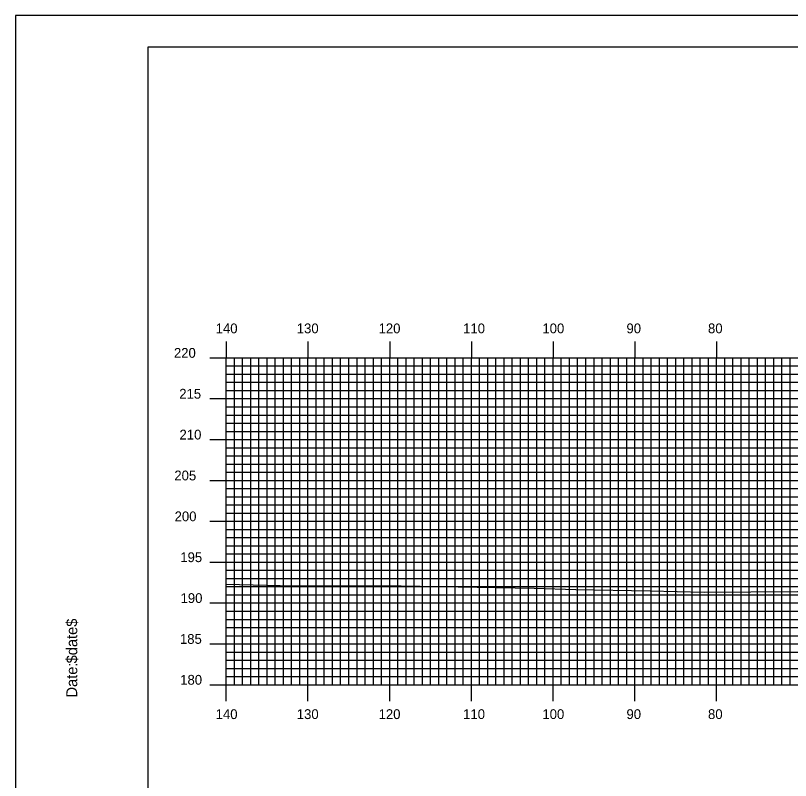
# Model space of a CAD drawing. Extents: x 1810980 to 1811323, y 442591 to 442811.
# Drawn here: x 1810980.1 to 1811074.9, y 442716.9 to 442810.5 of the extents above; entities that cross this region are included whole.
import ezdxf

# ---------------------------------------------------------------- set-up
doc = ezdxf.new("R2010")
doc.units = 0
for name, color, linetype in [('BORDER', 7, 'Continuous'), ('H_V ANNOTATION', 7, 'Continuous'), ('MAJOR', 7, 'Continuous'), ('MINOR', 7, 'Continuous'), ('PLOT BOUNDARY', 7, 'Continuous'), ('S_Roadway_Centerline', 7, 'Continuous')]:
    doc.layers.add(name, color=color, linetype=linetype)

msp = doc.modelspace()

# ---------------------------------------------------------------- linework, layer by layer
at = {"layer": 'BORDER'}
msp.add_lwpolyline([(1810996.29, 442596.665), (1811316.29, 442596.665), (1811316.29, 442806.665), (1810996.29, 442806.665)], close=True, dxfattribs=at)
at = {"layer": 'MAJOR'}
for p, q in [((1811005.89, 442770.669), (1811005.89, 442768.665)), ((1811015.89, 442770.669), (1811015.89, 442768.665)), ((1811025.89, 442770.669), (1811025.89, 442768.665)), ((1811035.89, 442770.669), (1811035.89, 442768.665)), ((1811045.89, 442770.669), (1811045.89, 442768.665)), ((1811055.89, 442770.669), (1811055.89, 442768.665)), ((1811065.89, 442770.669), (1811065.89, 442768.665)), ((1811003.886, 442768.665), (1811005.89, 442768.665)), ((1811005.89, 442768.665), (1811285.89, 442768.665)), ((1811005.89, 442728.665), (1811005.89, 442768.665)), ((1811005.89, 442728.665), (1811005.89, 442768.665)), ((1811005.89, 442768.665), (1811285.89, 442768.665)), ((1811015.89, 442728.665), (1811015.89, 442768.665)), ((1811025.89, 442728.665), (1811025.89, 442768.665)), ((1811035.89, 442728.665), (1811035.89, 442768.665)), ((1811045.89, 442728.665), (1811045.89, 442768.665)), ((1811055.89, 442728.665), (1811055.89, 442768.665)), ((1811065.89, 442728.665), (1811065.89, 442768.665)), ((1811003.886, 442763.665), (1811005.89, 442763.665)), ((1811005.89, 442763.665), (1811285.89, 442763.665)), ((1811003.886, 442758.665), (1811005.89, 442758.665)), ((1811005.89, 442758.665), (1811285.89, 442758.665)), ((1811003.886, 442753.665), (1811005.89, 442753.665)), ((1811005.89, 442753.665), (1811285.89, 442753.665)), ((1811003.886, 442748.665), (1811005.89, 442748.665)), ((1811005.89, 442748.665), (1811285.89, 442748.665)), ((1811003.886, 442743.665), (1811005.89, 442743.665)), ((1811005.89, 442743.665), (1811285.89, 442743.665)), ((1811003.886, 442738.665), (1811005.89, 442738.665)), ((1811005.89, 442738.665), (1811285.89, 442738.665)), ((1811003.886, 442733.665), (1811005.89, 442733.665)), ((1811005.89, 442733.665), (1811285.89, 442733.665)), ((1811003.886, 442728.665), (1811005.89, 442728.665)), ((1811005.89, 442728.665), (1811285.89, 442728.665)), ((1811005.89, 442728.665), (1811285.89, 442728.665)), ((1811005.89, 442726.661), (1811005.89, 442728.665)), ((1811015.89, 442726.661), (1811015.89, 442728.665)), ((1811025.89, 442726.661), (1811025.89, 442728.665)), ((1811035.89, 442726.661), (1811035.89, 442728.665)), ((1811045.89, 442726.661), (1811045.89, 442728.665)), ((1811055.89, 442726.661), (1811055.89, 442728.665)), ((1811065.89, 442726.661), (1811065.89, 442728.665))]:
    msp.add_line(p, q, dxfattribs=at)
at = {"layer": 'MINOR'}
for p, q in [((1811006.89, 442728.665), (1811006.89, 442768.665)), ((1811007.89, 442728.665), (1811007.89, 442768.665)), ((1811008.89, 442728.665), (1811008.89, 442768.665)), ((1811009.89, 442728.665), (1811009.89, 442768.665)), ((1811010.89, 442728.665), (1811010.89, 442768.665)), ((1811011.89, 442728.665), (1811011.89, 442768.665)), ((1811012.89, 442728.665), (1811012.89, 442768.665)), ((1811013.89, 442728.665), (1811013.89, 442768.665)), ((1811014.89, 442728.665), (1811014.89, 442768.665)), ((1811016.89, 442728.665), (1811016.89, 442768.665)), ((1811017.89, 442728.665), (1811017.89, 442768.665)), ((1811018.89, 442728.665), (1811018.89, 442768.665)), ((1811019.89, 442728.665), (1811019.89, 442768.665)), ((1811020.89, 442728.665), (1811020.89, 442768.665)), ((1811021.89, 442728.665), (1811021.89, 442768.665)), ((1811022.89, 442728.665), (1811022.89, 442768.665)), ((1811023.89, 442728.665), (1811023.89, 442768.665)), ((1811024.89, 442728.665), (1811024.89, 442768.665)), ((1811026.89, 442728.665), (1811026.89, 442768.665)), ((1811027.89, 442728.665), (1811027.89, 442768.665)), ((1811028.89, 442728.665), (1811028.89, 442768.665)), ((1811029.89, 442728.665), (1811029.89, 442768.665)), ((1811030.89, 442728.665), (1811030.89, 442768.665)), ((1811031.89, 442728.665), (1811031.89, 442768.665)), ((1811032.89, 442728.665), (1811032.89, 442768.665)), ((1811033.89, 442728.665), (1811033.89, 442768.665)), ((1811034.89, 442728.665), (1811034.89, 442768.665)), ((1811036.89, 442728.665), (1811036.89, 442768.665)), ((1811037.89, 442728.665), (1811037.89, 442768.665)), ((1811038.89, 442728.665), (1811038.89, 442768.665)), ((1811039.89, 442728.665), (1811039.89, 442768.665)), ((1811040.89, 442728.665), (1811040.89, 442768.665)), ((1811041.89, 442728.665), (1811041.89, 442768.665)), ((1811042.89, 442728.665), (1811042.89, 442768.665)), ((1811043.89, 442728.665), (1811043.89, 442768.665)), ((1811044.89, 442728.665), (1811044.89, 442768.665)), ((1811046.89, 442728.665), (1811046.89, 442768.665)), ((1811047.89, 442728.665), (1811047.89, 442768.665)), ((1811048.89, 442728.665), (1811048.89, 442768.665)), ((1811049.89, 442728.665), (1811049.89, 442768.665)), ((1811050.89, 442728.665), (1811050.89, 442768.665)), ((1811051.89, 442728.665), (1811051.89, 442768.665)), ((1811052.89, 442728.665), (1811052.89, 442768.665)), ((1811053.89, 442728.665), (1811053.89, 442768.665)), ((1811054.89, 442728.665), (1811054.89, 442768.665)), ((1811056.89, 442728.665), (1811056.89, 442768.665)), ((1811057.89, 442728.665), (1811057.89, 442768.665)), ((1811058.89, 442728.665), (1811058.89, 442768.665)), ((1811059.89, 442728.665), (1811059.89, 442768.665)), ((1811060.89, 442728.665), (1811060.89, 442768.665)), ((1811061.89, 442728.665), (1811061.89, 442768.665)), ((1811062.89, 442728.665), (1811062.89, 442768.665)), ((1811063.89, 442728.665), (1811063.89, 442768.665)), ((1811064.89, 442728.665), (1811064.89, 442768.665)), ((1811066.89, 442728.665), (1811066.89, 442768.665)), ((1811067.89, 442728.665), (1811067.89, 442768.665)), ((1811068.89, 442728.665), (1811068.89, 442768.665)), ((1811069.89, 442728.665), (1811069.89, 442768.665)), ((1811070.89, 442728.665), (1811070.89, 442768.665)), ((1811071.89, 442728.665), (1811071.89, 442768.665)), ((1811072.89, 442728.665), (1811072.89, 442768.665)), ((1811073.89, 442728.665), (1811073.89, 442768.665)), ((1811074.89, 442728.665), (1811074.89, 442768.665)), ((1811005.89, 442767.665), (1811285.89, 442767.665)), ((1811005.89, 442767.665), (1811007.894, 442767.665)), ((1811005.89, 442766.665), (1811285.89, 442766.665)), ((1811005.89, 442766.665), (1811007.894, 442766.665)), ((1811005.89, 442765.665), (1811285.89, 442765.665)), ((1811005.89, 442765.665), (1811007.894, 442765.665)), ((1811005.89, 442764.665), (1811285.89, 442764.665)), ((1811005.89, 442764.665), (1811007.894, 442764.665)), ((1811005.89, 442762.665), (1811285.89, 442762.665)), ((1811005.89, 442762.665), (1811007.894, 442762.665)), ((1811005.89, 442761.665), (1811285.89, 442761.665)), ((1811005.89, 442761.665), (1811007.894, 442761.665)), ((1811005.89, 442760.665), (1811285.89, 442760.665)), ((1811005.89, 442760.665), (1811007.894, 442760.665)), ((1811005.89, 442759.665), (1811285.89, 442759.665)), ((1811005.89, 442759.665), (1811007.894, 442759.665)), ((1811005.89, 442757.665), (1811285.89, 442757.665)), ((1811005.89, 442757.665), (1811007.894, 442757.665)), ((1811005.89, 442756.665), (1811285.89, 442756.665)), ((1811005.89, 442756.665), (1811007.894, 442756.665)), ((1811005.89, 442755.665), (1811285.89, 442755.665)), ((1811005.89, 442755.665), (1811007.894, 442755.665)), ((1811005.89, 442754.665), (1811285.89, 442754.665)), ((1811005.89, 442754.665), (1811007.894, 442754.665)), ((1811005.89, 442752.665), (1811285.89, 442752.665)), ((1811005.89, 442752.665), (1811007.894, 442752.665)), ((1811005.89, 442751.665), (1811285.89, 442751.665)), ((1811005.89, 442751.665), (1811007.894, 442751.665)), ((1811005.89, 442750.665), (1811285.89, 442750.665)), ((1811005.89, 442750.665), (1811007.894, 442750.665)), ((1811005.89, 442749.665), (1811285.89, 442749.665)), ((1811005.89, 442749.665), (1811007.894, 442749.665)), ((1811005.89, 442747.665), (1811285.89, 442747.665)), ((1811005.89, 442747.665), (1811007.894, 442747.665)), ((1811005.89, 442746.665), (1811285.89, 442746.665)), ((1811005.89, 442746.665), (1811007.894, 442746.665)), ((1811005.89, 442745.665), (1811285.89, 442745.665)), ((1811005.89, 442745.665), (1811007.894, 442745.665)), ((1811005.89, 442744.665), (1811285.89, 442744.665)), ((1811005.89, 442744.665), (1811007.894, 442744.665)), ((1811005.89, 442742.665), (1811285.89, 442742.665)), ((1811005.89, 442742.665), (1811007.894, 442742.665)), ((1811005.89, 442741.665), (1811285.89, 442741.665)), ((1811005.89, 442741.665), (1811007.894, 442741.665)), ((1811005.89, 442740.665), (1811285.89, 442740.665)), ((1811005.89, 442740.665), (1811007.894, 442740.665)), ((1811005.89, 442739.665), (1811285.89, 442739.665)), ((1811005.89, 442739.665), (1811007.894, 442739.665)), ((1811005.89, 442737.665), (1811285.89, 442737.665)), ((1811005.89, 442737.665), (1811007.894, 442737.665)), ((1811005.89, 442736.665), (1811285.89, 442736.665)), ((1811005.89, 442736.665), (1811007.894, 442736.665)), ((1811005.89, 442735.665), (1811285.89, 442735.665)), ((1811005.89, 442735.665), (1811007.894, 442735.665)), ((1811005.89, 442734.665), (1811285.89, 442734.665)), ((1811005.89, 442734.665), (1811007.894, 442734.665)), ((1811005.89, 442732.665), (1811285.89, 442732.665)), ((1811005.89, 442732.665), (1811007.894, 442732.665)), ((1811005.89, 442731.665), (1811285.89, 442731.665)), ((1811005.89, 442731.665), (1811007.894, 442731.665)), ((1811005.89, 442730.665), (1811285.89, 442730.665)), ((1811005.89, 442730.665), (1811007.894, 442730.665)), ((1811005.89, 442729.665), (1811285.89, 442729.665)), ((1811005.89, 442729.665), (1811007.894, 442729.665))]:
    msp.add_line(p, q, dxfattribs=at)
at = {"layer": 'PLOT BOUNDARY'}
msp.add_lwpolyline([(1810980.103, 442590.547), (1811320.103, 442590.547), (1811320.103, 442810.547), (1810980.103, 442810.547)], close=True, dxfattribs=at)
at = {"layer": 'S_Roadway_Centerline'}
msp.add_lwpolyline([(1811005.89, 442740.981), (1811014.13, 442740.752), (1811025.02, 442740.778), (1811027.304, 442740.754), (1811043.548, 442740.488), (1811048.646, 442740.324), (1811057.756, 442740.137), (1811064.376, 442740.008), (1811075.77, 442740.052), (1811082.957, 442740.087), (1811087.197, 442739.982), (1811096.319, 442739.788), (1811102.579, 442739.515), (1811107.932, 442739.559), (1811115.909, 442739.48), (1811119.943, 442739.613), (1811122.739, 442739.366), (1811132.296, 442739.098), (1811142.777, 442739.287), (1811145.974, 442739.298), (1811161.345, 442739.301), (1811166.62, 442739.104), (1811176.407, 442739.435)], dxfattribs=at)

# ---------------------------------------------------------------- texts
at = {"layer": 'BORDER'}
for s, p in [('$date$', (1810987.659, 442731.275)), ('Date:', (1810987.659, 442727.099))]:
    msp.add_text(s, height=1.3392, rotation=90, dxfattribs=at).set_placement(p)
at = {"layer": 'H_V ANNOTATION'}
for s, p in [('140', (1811004.595, 442771.665)), ('130', (1811014.52, 442771.665)), ('120', (1811024.53, 442771.665)), ('110', (1811034.873, 442771.665)), ('100', (1811044.573, 442771.665)), ('90', (1811054.862, 442771.665)), ('80', (1811064.84, 442771.665)), ('220', (1810999.485, 442768.665)), ('215', (1811000.139, 442763.665)), ('210', (1811000.171, 442758.665)), ('205', (1810999.539, 442753.665)), ('200', (1810999.571, 442748.665)), ('195', (1811000.267, 442743.665)), ('190', (1811000.299, 442738.665)), ('185', (1811000.224, 442733.665)), ('180', (1811000.256, 442728.665)), ('140', (1811004.595, 442724.465)), ('130', (1811014.52, 442724.465)), ('120', (1811024.53, 442724.465)), ('110', (1811034.873, 442724.465)), ('100', (1811044.573, 442724.465)), ('90', (1811054.862, 442724.465)), ('80', (1811064.84, 442724.465))]:
    msp.add_text(s, height=1.2, dxfattribs=at).set_placement(p)
at = {"layer": 'MAJOR'}
msp.add_text('-', height=0.012, dxfattribs=at).set_placement((1811005.881, 442728.665))

doc.saveas('drawing.dxf')
